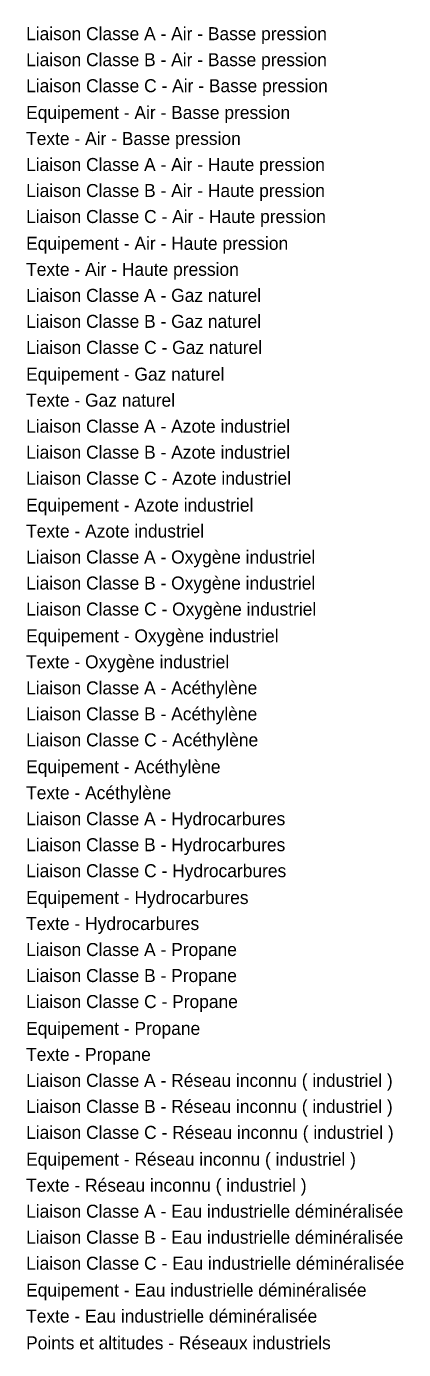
# Model space of a CAD drawing. Extents: x 703432 to 707394, y 7057985 to 7059523.
# Drawn here: x 707231.2 to 707245.7, y 7058478.4 to 7058529.3 of the extents above; entities that cross this region are included whole.
import ezdxf

# ---------------------------------------------------------------- set-up
doc = ezdxf.new("R2010")
doc.units = 0
for name, color, linetype in [('R_IND_ACETYLENE_CANALISATION_CL_A', 7, 'Continuous'), ('R_IND_ACETYLENE_CANALISATION_CL_B', 7, 'Continuous'), ('R_IND_ACETYLENE_CANALISATION_CL_C', 7, 'Continuous'), ('R_IND_ACETYLENE_EQUIP', 7, 'Continuous'), ('R_IND_ACETYLENE_TEXTE', 7, 'Continuous'), ('R_IND_AIR_BP_CANALISATION_CL_A', 7, 'Continuous'), ('R_IND_AIR_BP_CANALISATION_CL_B', 7, 'Continuous'), ('R_IND_AIR_BP_CANALISATION_CL_C', 7, 'Continuous'), ('R_IND_AIR_BP_EQUIP', 7, 'Continuous'), ('R_IND_AIR_BP_TEXTE', 7, 'Continuous'), ('R_IND_AIR_HP_CANALISATION_CL_A', 7, 'Continuous'), ('R_IND_AIR_HP_CANALISATION_CL_B', 7, 'Continuous'), ('R_IND_AIR_HP_CANALISATION_CL_C', 7, 'Continuous'), ('R_IND_AIR_HP_EQUIP', 7, 'Continuous'), ('R_IND_AIR_HP_TEXTE', 7, 'Continuous'), ('R_IND_ALT_POINT', 7, 'Continuous'), ('R_IND_AZOTE_CANALISATION_CL_A', 7, 'Continuous'), ('R_IND_AZOTE_CANALISATION_CL_B', 7, 'Continuous'), ('R_IND_AZOTE_CANALISATION_CL_C', 7, 'Continuous'), ('R_IND_AZOTE_EQUIP', 7, 'Continuous'), ('R_IND_AZOTE_TEXTE', 7, 'Continuous'), ('R_IND_EAU_DEMINERALISEE_CANALISATION_CL_A', 7, 'Continuous'), ('R_IND_EAU_DEMINERALISEE_CANALISATION_CL_B', 7, 'Continuous'), ('R_IND_EAU_DEMINERALISEE_CANALISATION_CL_C', 7, 'Continuous'), ('R_IND_EAU_DEMINERALISEE_EQUIP', 7, 'Continuous'), ('R_IND_EAU_DEMINERALISEE_TEXTE', 7, 'Continuous'), ('R_IND_GAZ_NAT_CANALISATION_CL_A', 7, 'Continuous'), ('R_IND_GAZ_NAT_CANALISATION_CL_B', 7, 'Continuous'), ('R_IND_GAZ_NAT_CANALISATION_CL_C', 7, 'Continuous'), ('R_IND_GAZ_NAT_EQUIP', 7, 'Continuous'), ('R_IND_GAZ_NAT_TEXTE', 7, 'Continuous'), ('R_IND_HYDROCARBURE_CANALISATION_CL_A', 7, 'Continuous'), ('R_IND_HYDROCARBURE_CANALISATION_CL_B', 7, 'Continuous'), ('R_IND_HYDROCARBURE_CANALISATION_CL_C', 7, 'Continuous'), ('R_IND_HYDROCARBURE_EQUIP', 7, 'Continuous'), ('R_IND_HYDROCARBURE_TEXTE', 7, 'Continuous'), ('R_IND_INDUS_INCON_CANALISATION_CL_B', 7, 'Continuous'), ('R_IND_INDUS_INCON_CANALISATION_CL_C', 7, 'Continuous'), ('R_IND_INDUS_INCON_EQUIP', 7, 'Continuous'), ('R_IND_INDUS_INCON_TEXTE', 7, 'Continuous'), ('R_IND_OXYGENE_CANALISATION_CL_A', 7, 'Continuous'), ('R_IND_OXYGENE_CANALISATION_CL_B', 7, 'Continuous'), ('R_IND_OXYGENE_CANALISATION_CL_C', 7, 'Continuous'), ('R_IND_OXYGENE_EQUIP', 7, 'Continuous'), ('R_IND_OXYGENE_TEXTE', 7, 'Continuous'), ('R_IND_PROPANE_CANALISATION_CL_A', 7, 'Continuous'), ('R_IND_PROPANE_CANALISATION_CL_B', 7, 'Continuous'), ('R_IND_PROPANE_CANALISATION_CL_C', 7, 'Continuous'), ('R_IND_PROPANE_EQUIP', 7, 'Continuous'), ('R_IND_PROPANE_TEXTE', 7, 'Continuous')]:
    doc.layers.add(name, color=color, linetype=linetype)

msp = doc.modelspace()

# ---------------------------------------------------------------- texts
at = {"layer": 'R_IND_ACETYLENE_CANALISATION_CL_A'}
msp.add_text('Liaison Classe A - Acéthylène', height=0.5, dxfattribs=at).set_placement((707231.222, 7058503.606))
at = {"layer": 'R_IND_ACETYLENE_CANALISATION_CL_B'}
msp.add_text('Liaison Classe B - Acéthylène', height=0.5, dxfattribs=at).set_placement((707231.222, 7058502.606))
at = {"layer": 'R_IND_ACETYLENE_CANALISATION_CL_C'}
msp.add_text('Liaison Classe C - Acéthylène', height=0.5, dxfattribs=at).set_placement((707231.222, 7058501.606))
at = {"layer": 'R_IND_ACETYLENE_EQUIP'}
msp.add_text('Equipement - Acéthylène', height=0.5, dxfattribs=at).set_placement((707231.222, 7058500.575))
at = {"layer": 'R_IND_ACETYLENE_TEXTE'}
msp.add_text('Texte - Acéthylène', height=0.5, dxfattribs=at).set_placement((707231.222, 7058499.575))
at = {"layer": 'R_IND_AIR_BP_CANALISATION_CL_A'}
msp.add_text('Liaison Classe A - Air - Basse pression', height=0.5, dxfattribs=at).set_placement((707231.222, 7058528.761))
at = {"layer": 'R_IND_AIR_BP_CANALISATION_CL_B'}
msp.add_text('Liaison Classe B - Air - Basse pression', height=0.5, dxfattribs=at).set_placement((707231.222, 7058527.761))
at = {"layer": 'R_IND_AIR_BP_CANALISATION_CL_C'}
msp.add_text('Liaison Classe C - Air - Basse pression', height=0.5, dxfattribs=at).set_placement((707231.222, 7058526.761))
at = {"layer": 'R_IND_AIR_BP_EQUIP'}
msp.add_text('Equipement - Air - Basse pression', height=0.5, dxfattribs=at).set_placement((707231.222, 7058525.73))
at = {"layer": 'R_IND_AIR_BP_TEXTE'}
msp.add_text('Texte - Air - Basse pression', height=0.5, dxfattribs=at).set_placement((707231.222, 7058524.73))
at = {"layer": 'R_IND_AIR_HP_CANALISATION_CL_A'}
msp.add_text('Liaison Classe A - Air - Haute pression', height=0.5, dxfattribs=at).set_placement((707231.222, 7058523.73))
at = {"layer": 'R_IND_AIR_HP_CANALISATION_CL_B'}
msp.add_text('Liaison Classe B - Air - Haute pression', height=0.5, dxfattribs=at).set_placement((707231.222, 7058522.73))
at = {"layer": 'R_IND_AIR_HP_CANALISATION_CL_C'}
msp.add_text('Liaison Classe C - Air - Haute pression', height=0.5, dxfattribs=at).set_placement((707231.222, 7058521.73))
at = {"layer": 'R_IND_AIR_HP_EQUIP'}
msp.add_text('Equipement - Air - Haute pression', height=0.5, dxfattribs=at).set_placement((707231.222, 7058520.699))
at = {"layer": 'R_IND_AIR_HP_TEXTE'}
msp.add_text('Texte - Air - Haute pression', height=0.5, dxfattribs=at).set_placement((707231.222, 7058519.699))
at = {"layer": 'R_IND_ALT_POINT'}
msp.add_text('Points et altitudes - Réseaux industriels', height=0.5, dxfattribs=at).set_placement((707231.222, 7058478.42))
at = {"layer": 'R_IND_AZOTE_CANALISATION_CL_A'}
msp.add_text('Liaison Classe A - Azote industriel', height=0.5, dxfattribs=at).set_placement((707231.222, 7058513.668))
at = {"layer": 'R_IND_AZOTE_CANALISATION_CL_B'}
msp.add_text('Liaison Classe B - Azote industriel', height=0.5, dxfattribs=at).set_placement((707231.222, 7058512.668))
at = {"layer": 'R_IND_AZOTE_CANALISATION_CL_C'}
msp.add_text('Liaison Classe C - Azote industriel', height=0.5, dxfattribs=at).set_placement((707231.222, 7058511.668))
at = {"layer": 'R_IND_AZOTE_EQUIP'}
msp.add_text('Equipement - Azote industriel', height=0.5, dxfattribs=at).set_placement((707231.222, 7058510.637))
at = {"layer": 'R_IND_AZOTE_TEXTE'}
msp.add_text('Texte - Azote industriel', height=0.5, dxfattribs=at).set_placement((707231.222, 7058509.637))
at = {"layer": 'R_IND_EAU_DEMINERALISEE_CANALISATION_CL_A'}
msp.add_text('Liaison Classe A - Eau industrielle déminéralisée', height=0.5, dxfattribs=at).set_placement((707231.222, 7058483.482))
at = {"layer": 'R_IND_EAU_DEMINERALISEE_CANALISATION_CL_B'}
msp.add_text('Liaison Classe B - Eau industrielle déminéralisée', height=0.5, dxfattribs=at).set_placement((707231.222, 7058482.482))
at = {"layer": 'R_IND_EAU_DEMINERALISEE_CANALISATION_CL_C'}
msp.add_text('Liaison Classe C - Eau industrielle déminéralisée', height=0.5, dxfattribs=at).set_placement((707231.222, 7058481.482))
at = {"layer": 'R_IND_EAU_DEMINERALISEE_EQUIP'}
msp.add_text('Equipement - Eau industrielle déminéralisée', height=0.5, dxfattribs=at).set_placement((707231.222, 7058480.451))
at = {"layer": 'R_IND_EAU_DEMINERALISEE_TEXTE'}
msp.add_text('Texte - Eau industrielle déminéralisée', height=0.5, dxfattribs=at).set_placement((707231.222, 7058479.451))
at = {"layer": 'R_IND_GAZ_NAT_CANALISATION_CL_A'}
msp.add_text('Liaison Classe A - Gaz naturel', height=0.5, dxfattribs=at).set_placement((707231.222, 7058518.699))
at = {"layer": 'R_IND_GAZ_NAT_CANALISATION_CL_B'}
msp.add_text('Liaison Classe B - Gaz naturel', height=0.5, dxfattribs=at).set_placement((707231.222, 7058517.699))
at = {"layer": 'R_IND_GAZ_NAT_CANALISATION_CL_C'}
msp.add_text('Liaison Classe C - Gaz naturel', height=0.5, dxfattribs=at).set_placement((707231.222, 7058516.699))
at = {"layer": 'R_IND_GAZ_NAT_EQUIP'}
msp.add_text('Equipement - Gaz naturel', height=0.5, dxfattribs=at).set_placement((707231.222, 7058515.668))
at = {"layer": 'R_IND_GAZ_NAT_TEXTE'}
msp.add_text('Texte - Gaz naturel', height=0.5, dxfattribs=at).set_placement((707231.222, 7058514.668))
at = {"layer": 'R_IND_HYDROCARBURE_CANALISATION_CL_A'}
msp.add_text('Liaison Classe A - Hydrocarbures', height=0.5, dxfattribs=at).set_placement((707231.222, 7058498.575))
at = {"layer": 'R_IND_HYDROCARBURE_CANALISATION_CL_B'}
msp.add_text('Liaison Classe B - Hydrocarbures', height=0.5, dxfattribs=at).set_placement((707231.222, 7058497.575))
at = {"layer": 'R_IND_HYDROCARBURE_CANALISATION_CL_C'}
msp.add_text('Liaison Classe C - Hydrocarbures', height=0.5, dxfattribs=at).set_placement((707231.222, 7058496.575))
at = {"layer": 'R_IND_HYDROCARBURE_EQUIP'}
msp.add_text('Equipement - Hydrocarbures', height=0.5, dxfattribs=at).set_placement((707231.222, 7058495.544))
at = {"layer": 'R_IND_HYDROCARBURE_TEXTE'}
msp.add_text('Texte - Hydrocarbures', height=0.5, dxfattribs=at).set_placement((707231.222, 7058494.544))
at = {"layer": 'R_IND_INDUS_INCON_CANALISATION_CL_B'}
msp.add_text('Liaison Classe B - Réseau inconnu ( industriel )', height=0.5, dxfattribs=at).set_placement((707231.222, 7058487.513))
at = {"layer": 'R_IND_INDUS_INCON_CANALISATION_CL_C'}
for s, p in [('Liaison Classe A - Réseau inconnu ( industriel )', (707231.222, 7058488.513)), ('Liaison Classe C - Réseau inconnu ( industriel )', (707231.222, 7058486.513))]:
    msp.add_text(s, height=0.5, dxfattribs=at).set_placement(p)
at = {"layer": 'R_IND_INDUS_INCON_EQUIP'}
msp.add_text('Equipement - Réseau inconnu ( industriel )', height=0.5, dxfattribs=at).set_placement((707231.222, 7058485.482))
at = {"layer": 'R_IND_INDUS_INCON_TEXTE'}
msp.add_text('Texte - Réseau inconnu ( industriel )', height=0.5, dxfattribs=at).set_placement((707231.222, 7058484.482))
at = {"layer": 'R_IND_OXYGENE_CANALISATION_CL_A'}
msp.add_text('Liaison Classe A - Oxygène industriel', height=0.5, dxfattribs=at).set_placement((707231.222, 7058508.637))
at = {"layer": 'R_IND_OXYGENE_CANALISATION_CL_B'}
msp.add_text('Liaison Classe B - Oxygène industriel', height=0.5, dxfattribs=at).set_placement((707231.222, 7058507.637))
at = {"layer": 'R_IND_OXYGENE_CANALISATION_CL_C'}
msp.add_text('Liaison Classe C - Oxygène industriel', height=0.5, dxfattribs=at).set_placement((707231.222, 7058506.637))
at = {"layer": 'R_IND_OXYGENE_EQUIP'}
msp.add_text('Equipement - Oxygène industriel', height=0.5, dxfattribs=at).set_placement((707231.222, 7058505.606))
at = {"layer": 'R_IND_OXYGENE_TEXTE'}
msp.add_text('Texte - Oxygène industriel', height=0.5, dxfattribs=at).set_placement((707231.222, 7058504.606))
at = {"layer": 'R_IND_PROPANE_CANALISATION_CL_A'}
msp.add_text('Liaison Classe A - Propane', height=0.5, dxfattribs=at).set_placement((707231.222, 7058493.544))
at = {"layer": 'R_IND_PROPANE_CANALISATION_CL_B'}
msp.add_text('Liaison Classe B - Propane', height=0.5, dxfattribs=at).set_placement((707231.222, 7058492.544))
at = {"layer": 'R_IND_PROPANE_CANALISATION_CL_C'}
msp.add_text('Liaison Classe C - Propane', height=0.5, dxfattribs=at).set_placement((707231.222, 7058491.544))
at = {"layer": 'R_IND_PROPANE_EQUIP'}
msp.add_text('Equipement - Propane', height=0.5, dxfattribs=at).set_placement((707231.222, 7058490.513))
at = {"layer": 'R_IND_PROPANE_TEXTE'}
msp.add_text('Texte - Propane', height=0.5, dxfattribs=at).set_placement((707231.222, 7058489.513))

doc.saveas('drawing.dxf')
